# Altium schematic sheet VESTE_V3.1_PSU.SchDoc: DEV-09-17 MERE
size A3; Date: 22/11/2017; Organization: Altium Limited; Address1: L3, 12a Rodborough Rd; Address2: Frenchs Forest; Address3: NSW; Address4: Australia 2086; Revision: 1.0; SheetNumber: 2; SheetTotal: 2; PageSetup: Record=PageOptions¦CenterHorizontal=True¦CenterVertical=True¦PrintScale=0.97¦XCorrection=1.00¦YCorrection=1.00¦PrintKind=0¦BorderSize=5000000¦LeftOffset=0¦BottomOffset=0¦Orientation=2¦PaperLength=1000¦PaperWidth=1000¦Scale=100¦PaperSource=7¦PrintQuality=-3¦MediaType=1¦DitherType=10¦PaperKind=A4¦PrintScaleMode=1
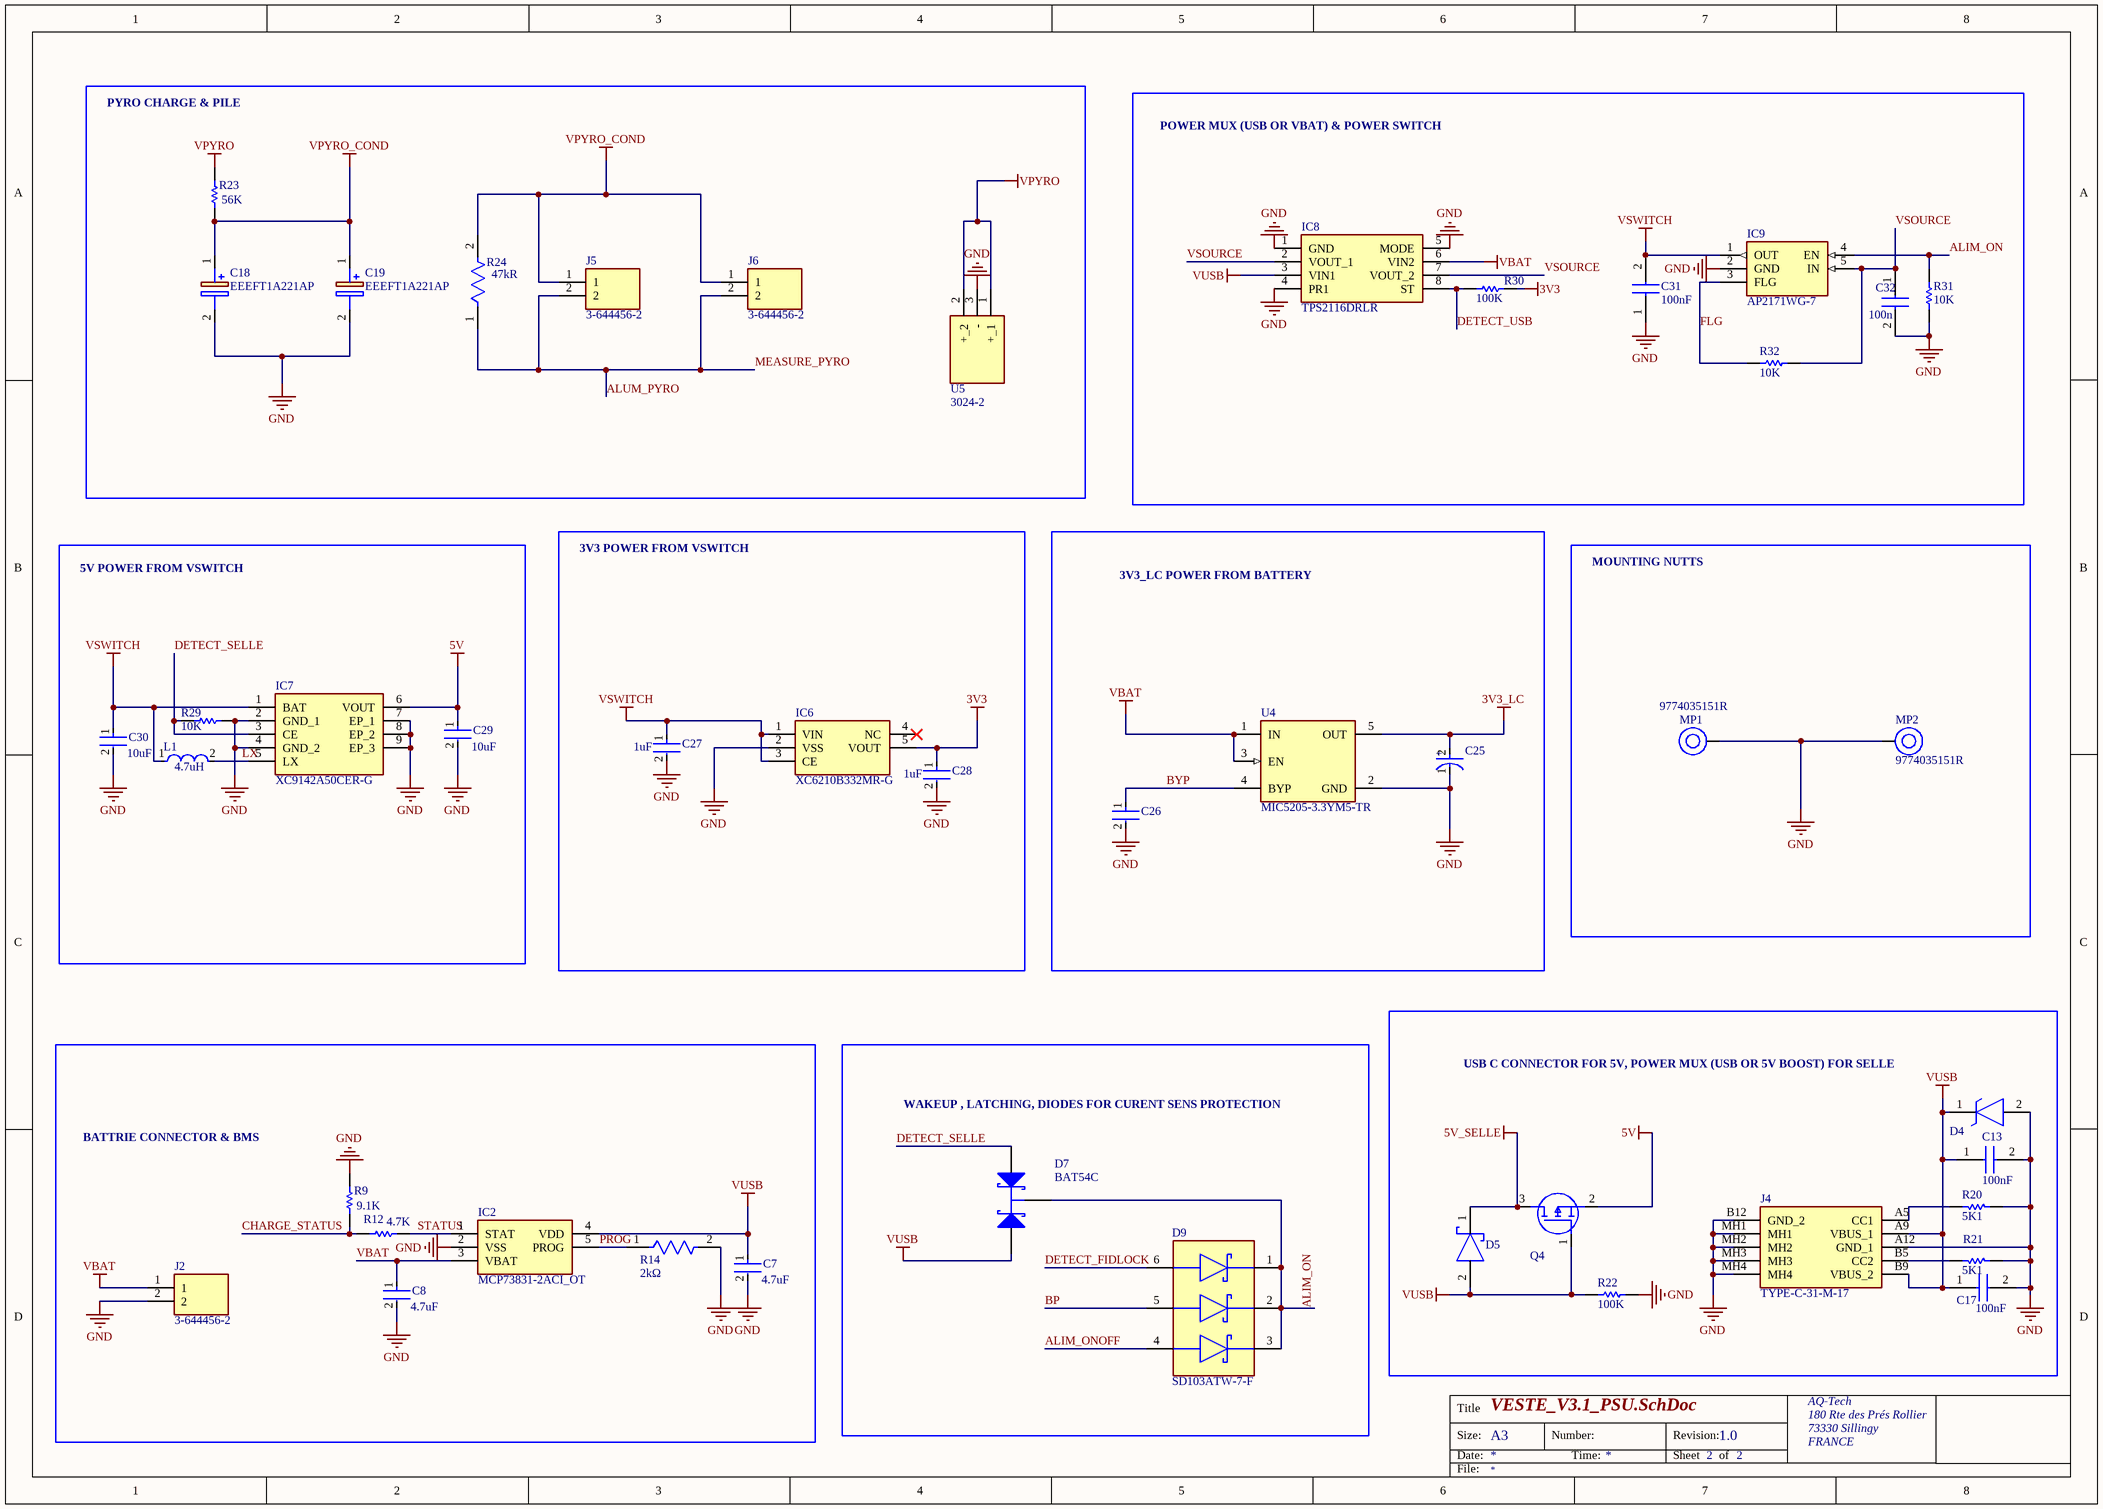
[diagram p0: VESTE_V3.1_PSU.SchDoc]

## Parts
C7  Capacitance: 4.7uF  [FP-CL828-IPC_C]  (hidden comment: CL05A475KP5NRNC)
C8  Capacitance: 4.7uF  [FP-CL828-IPC_C]  (hidden comment: CL05A475KP5NRNC)
C13  Capacitance: 100nF  [CAPC1608X90N]
C17  Capacitance: 100nF  [CAPC1608X90N]
C18  EEEFT1A221AP  [EEE1AA101SP]
C19  EEEFT1A221AP  [EEE1AA101SP]
C25  TAJA225K016RNJ  [FP-TAJA-MFG]  (value not drawn)
C26  CL05B471KB5NNNC  [FP-CL23-IPC_C]  (value not drawn)
C27  Capacitance: 1uF  [FP-CL511-IPC_C]  (hidden comment: CL05A105KP5NNNC)
C28  Capacitance: 1uF  [FP-CL511-IPC_C]  (hidden comment: CL05A105KP5NNNC)
C29  Capacitance: 10uF  [FP-CL05A106MP5NUNC-MFG]  (hidden comment: CL05A106MP5NUNC)
C30  Capacitance: 10uF  [FP-CL05A106MP5NUNC-MFG]  (hidden comment: CL05A106MP5NUNC)
C31  Capacitance: 100nF  [CAPC1608X90N]
C32  Capacitance: 100n  [CAPC1608X90N]
D4  D5V0M1U2S9Q-7  [SODFL1006X40N]  (value not drawn)
D5  RB168MM100TR  [FP-PMDU-MFG]  (value not drawn)
D7  BAT54C  [NXP-SOT23-3_V]
D9  SD103ATW-7-F  [FP-SOT363-IPC_A]
IC2  MCP73831-2ACI_OT  [SOT95P270X145-5N]
IC6  XC6210B332MR-G  [SOT95P280X130-5N]
IC7  XC9142A50CER-G  [XC9142A50CERG]
IC8  TPS2116DRLR  [SOTFL50P160X60-8N]
IC9  AP2171WG-7  [SOT95P282X130-5N]
J2  3-644456-2  [HDRV2W67P0X254_1X2_478X234X1029P]
J4  TYPE-C-31-M-17  [TYPEC31M17]
J5  3-644456-2  [HDRV2W67P0X254_1X2_478X234X1029P]
J6  3-644456-2  [HDRV2W67P0X254_1X2_478X234X1029P]
L1  Inductance: 4.7uH  [FP-LQH5BPB_T0-MFG]  (hidden comment: LQH5BPN4R7NT0L)
MP1  9774035151R  [9774035151]
MP2  9774035151R  [9774035151]
Q4  DMP3125L-7  [SOT96P240X110-3N]  (value not drawn)
R9  Resistance: 9.1K  [RESC1005X40X25NL05T10]  (hidden comment: RC0402FR-079K1L)
R12  Resistance: 4.7K  [RESC1005X40X25NL05T10]  (hidden comment: RC0402FR-074K7L)
R14  Resistance: 2kΩ  [FP-RC_L0402-MFG]  (hidden comment: RC0402FR-072KL)
R20  Resistance: 5K1  [RESC1005X40X25NL05T10]  (hidden comment: RC0402FR-075K1L)
R21  Resistance: 5K1  [RESC1005X40X25NL05T10]  (hidden comment: RC0402FR-075K1L)
R22  Resistance: 100K  [RESC1005X40X25NL05T10]  (hidden comment: RC0402FR-07100KL)
R23  Resistance: 56K  [RESC1005X40X25ML05T10]  (hidden comment: RC0402FR-0756KL)
R24  Resistance: 47kR  [FP-RC0603FR-0747KL-MFG]  (hidden comment: RC0603FR-0747KL)
R29  Resistance: 10K  [RESC1005X40X25ML05T05]  (hidden comment: ERJ-2GEJ103X)
R30  Resistance: 100K  [RESC1005X40X25NL05T10]  (hidden comment: RC0402FR-07100KL)
R31  Resistance: 10K  [RESC1005X40X25ML05T05]  (hidden comment: ERJ-2GEJ103X)
R32  Resistance: 10K  [RESC1005X40X25ML05T05]  (hidden comment: ERJ-2GEJ103X)
U4  MIC5205-3.3YM5-TR  [FP-M5-MFG]
U5  3024-2  [30242]

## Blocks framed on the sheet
PYRO CHARGE & PILE: C18 C19 J5 J6 R23 R24 U5
POWER MUX (USB OR VBAT) & POWER SWITCH: C31 C32 IC8 IC9 R30-R32
5V POWER FROM VSWITCH: C29 C30 IC7 L1 R29
3V3 POWER FROM VSWITCH: C27 C28 IC6
3V3_LC POWER FROM BATTERY: C25 C26 U4
MOUNTING NUTTS: MP1 MP2
BATTRIE CONNECTOR & BMS: C7 C8 IC2 J2 R9 R12 R14
WAKEUP , LATCHING, DIODES FOR CURENT SENS PROTECTION: D7 D9

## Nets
3V3: C28.1 IC6.5(VOUT) R30.1
3V3_LC: C25.2(A) U4.5(OUT)
5V: C29.1 IC7.6(VOUT) Q4.2(S)
5V_SELLE: D5.1(C) Q4.3(D)
GND: C7.2 C8.2 C13.2 C17.2 C18.2(-) C19.2(-) C25.1(C) C26.2 C27.2 C28.2 C29.2 C30.2 C31.1 C32.2 D4.2(A) IC2.2(VSS) IC6.2(VSS) IC7.2(GND_1) IC7.4(GND_2) IC7.7(EP_1) IC7.8(EP_2) IC7.9(EP_3) IC8.1(GND) IC8.4(PR1) IC8.5(MODE) IC9.2(GND) J2.2 J4.A12(GND_1) J4.B12(GND_2) J4.MH1 J4.MH2 J4.MH3 J4.MH4 MP1.1 MP2.1 R9.2 R14.2 R20.1 R21.1 R22.1 R29.2 R31.2 U4.2(GND) U5.3(-)
VBAT: C8.1 IC2.3(VBAT) IC8.6(VIN2) J2.1 U4.1(IN) U4.3(EN)
VPYRO: R23.2 U5.1(+_1) U5.2(+_2)
VPYRO_COND: C18.1(+) C19.1(+) J5.1 J6.1 R23.1 R24.2
VSWITCH: C27.1 C30.1 C31.2 IC6.1(VIN) IC6.3(CE) IC7.1(BAT) IC9.1(OUT) L1.1
VUSB: C7.1 C13.1 C17.1 D4.1(K) D5.2(A) D7.2(A) IC2.4(VDD) IC8.3(VIN1) J4.A9(VBUS_1) J4.B9(VBUS_2) Q4.1(G) R22.2
ALIM_ON: D7.3(K) D9.1(1_CATHODE) D9.2(2_CATHODE) D9.3(3_CATHODE) IC9.4(EN) R31.1
ALIM_ONOFF: D9.4(3_ANODE)
ALUM_PYRO: J5.2 J6.2 R24.1  [also labelled MEASURE_PYRO]
BP: D9.5(2_ANODE)
BYP: C26.1 U4.4(BYP)
CHARGE_STATUS: R9.1 R12.1
DETECT_FIDLOCK: D9.6(1_ANODE)
DETECT_SELLE: D7.1(A) IC7.3(CE) R29.1
DETECT_USB: IC8.8(ST) R30.2
FLG: IC9.3(FLG) R32.1
LX: IC7.5(LX) L1.2
PROG: IC2.5(PROG) R14.1
STATUS: IC2.1(STAT) R12.2
VSOURCE: C32.1 IC8.2(VOUT_1) IC8.7(VOUT_2) IC9.5(IN) R32.2
NetJ4_A5: J4.A5(CC1) R20.2
NetJ4_B5: J4.B5(CC2) R21.2

Not connected (* = marked no-connect by the designer): IC6 4(NC)*

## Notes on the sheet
- USB C CONNECTOR FOR 5V, POWER MUX (USB OR 5V BOOST) FOR SELLE

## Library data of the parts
C7 C8 = CMP-13271-001251-1: Cap Ceramic 4.7uF 10V X5R ±10% SMD 0402 +85°C Paper T/R
C13 C17 C31 C32 = CL10B104KB8NNNC: Capacitor; Manufacturer_Name: SAMSUNG
C18 C19 = EEEFT1A221AP: Capacitor Polarised; Manufacturer_Name: Panasonic
C25 = CMP-04424-000432-1: 2.2uF 16V  ±10% 6.5Ω 1206  SMD Tantalum Capacitor; Polarity: Polar; Leakage Current: 500nA; Dissipation Factor: 6%; ESR (Equivalent Series Resistance): 6.5R; Q Factor: 6
C26 = CMP-13271-000495-1: Cap Ceramic 470pF 50V X7R ±10% SMD 0402 +125°C Paper T/R
C27 C28 = CMP-13271-001936-1: Cap Ceramic 1uF 10V X5R ±10% SMD 0402 +85°C Paper T/R
C29 C30 = CMP-13271-000002-1: CAP CER 10UF 10V X5R 0402; Manufacturer: Samsung; Temperature Coefficient: 15%; Tolerance: 20%; Material: Ceramic
D4 = D5V0M1U2S9Q-7: TVS Diode (Uni-directional); Manufacturer_Name: Diodes Inc.
D5 = CMP-08971-000001-1: DIODE SCHOTTKY 100V 1A SOD123FL; Manufacturer: ROHM Semiconductor; Max Surge Forward Current: 40A; Max Junction Temp: +150°C; Peak Reverse Current: 0.4uA
D7 = CMP-0417-00003-1: Schottky Barrier Diode, 30 V, 2 uA, -55 to 150 degC, 3-Pin SOT23, RoHS, Tape and Reel; Manufacturer: NXP Semiconductors; IR (uA): 2; VF (mV): 800; Trr (ns): 5; Cd (pF): 10; VR (V): 30; Rth(j-a) (K/W): 500
D9 = CMP-12790-000076-1: DIODE ARRAY SCHOTTKY 40V SOT363; Current Rating: 350mA; Forward Voltage: 500mV; Peak Non-Repetitive Surge Current: 1A; Peak Reverse Current: 5uA; Power Rating: 200mW; Reverse Recovery Time: 10ns; Capacitance: 50pF; Average Rectified Current: 175mA
IC2 = MCP73831-2ACI_OT: Integrated Circuit; Manufacturer_Name: Microchip; Manufacturer_Part_Number: MCP73831-2ACI/OT
IC6 = XC6210B332MR-G: Integrated Circuit; Manufacturer_Name: Torex
IC7 = XC9142A50CER-G: Integrated Circuit; Manufacturer_Name: Torex
IC8 = TPS2116DRLR: Integrated Circuit; Manufacturer_Name: Texas Instruments
IC9 = AP2171WG-7: Integrated Circuit; Manufacturer_Name: Diodes Inc.
J2 J5 J6 = 3-644456-2: Connector; Manufacturer_Name: TE Connectivity
J4 = TYPE-C-31-M-17: Connector; Manufacturer_Name: Korean Hroparts Elec
L1 = CMP-06042-004027-1: Wire Wound Ferrite Inductor for Power Lines 4.7μH ±30% 0.0696Ω 2.0A 2020; Shielding: Shielded; DC Resistance (DCR): 58mR; Current Rating: 2A; Max DC Current: 3A; Test Frequency: 100kHz; Self Resonant Frequency: 40MHz
MP1 MP2 = CMP-03913-118307956-1: 9774035151R WA-SMSI SMT Steel Spacer, M2.5 Internal non Stop
Q4 = DMP3125L-7: MOSFET (P-Channel); Manufacturer_Name: Diodes Inc.
R9 = CMP-2002-07017-1: Manufacturer: Yageo / Phycomp
R12 = CMP-1011-00586-2: Manufacturer: Yageo / Phycomp
R14 = CMP-2002-07580-2: RES SMD 2K OHM 1% 1/16W 0402; Manufacturer: Yageo; Voltage Rating: 50V; Temperature Coefficient: 100ppm/°C; Power Rating: 0.0625W; Standoff Height: 0mm; Value: 2kΩ
R20 R21 = CMP-2002-07753-1: Manufacturer: Yageo / Phycomp
R22 R30 = CMP-2002-07343-1: Manufacturer: Yageo / Phycomp
R23 = CMP-1011-00708-2: Manufacturer: Yageo / Phycomp
R24 = CMP-1659-00055-2: RES SMD 47K OHM 1% 1/10W 0603; Voltage Rating: 50V; Temperature Coefficient: 100ppm/°C; Max Power Dissipation: 100mW
R29 R31 R32 = CMP-2002-00433-1: Manufacturer: Panasonic
U4 = CMP-06324-000014-1: IC REG LINEAR 3.3V 150MA SOT23-5; Manufacturer: Microchip; Number Of Outputs: 1; Output Type: Fixed; Min Supply Voltage: 2.5V; Accuracy Percentage: 2%; Dropout Voltage: 165mV; Max Supply Voltage: 16V; Max Junction Temp: +125°C; Standoff Height: 0mm
U5 = 3024-2: Undefined or Miscellaneous; Manufacturer_Name: Keystone Electronics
